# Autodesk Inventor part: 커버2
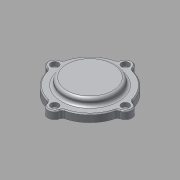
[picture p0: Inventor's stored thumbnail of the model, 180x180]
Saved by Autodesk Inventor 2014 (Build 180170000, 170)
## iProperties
Company: 한국ATC센터
Created: 2015-12
Part Number: 커버2
Document SubType Name: Modeling
Designer: mdu
Density: 2.71 g/cm^3
Material: 알루미늄 6061
Appearance: 알루미늄 - 평지
Author: mdu
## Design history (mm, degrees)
sketch "스케치1"
  geometry: C1 r 1.621 at (0, 6.75) reference; C2 r 1.621 at (-37, -30.25) reference; C3 r 1.621 at (0, -67.25) reference; C4 r 1.621 at (37, -30.25) reference; C5 r 10 at (0, -30.25) reference; C6 r 12 at (0, -30.25); C7 r 24.5 at (0, -30.25) reference; A1 r 3 centre (-38.77, -20.408) between (-38.239, -23.361) and (-35.862, -21.146) reference; A2 r 7 centre (-37, -30.25) between (-38.239, -23.361) and (-38.239, -37.139) reference; A3 r 3 centre (-38.77, -40.092) between (-35.862, -39.354) and (-38.239, -37.139) reference; A4 r 37 centre (0, -30.25) between (-35.862, -39.354) and (-9.104, -66.113) reference; A5 r 3 centre (-9.842, -69.02) between (-6.889, -68.489) and (-9.104, -66.113) reference; A6 r 7 centre (0, -67.25) between (-6.889, -68.489) and (6.889, -68.489) reference; A7 r 3 centre (9.842, -69.02) between (9.104, -66.112) and (6.889, -68.489) reference; A8 r 37 centre (0, -30.25) between (9.104, -66.112) and (35.863, -39.354) reference; A9 r 3 centre (38.77, -40.092) between (38.239, -37.139) and (35.863, -39.354) reference; A10 r 7 centre (37, -30.25) between (38.239, -37.139) and (38.239, -23.361) reference; A11 r 3 centre (38.77, -20.408) between (35.863, -21.146) and (38.239, -23.361) reference; A12 r 37 centre (0, -30.25) between (35.863, -21.146) and (9.104, 5.612) reference; A13 r 3 centre (9.842, 8.52) between (6.889, 7.989) and (9.104, 5.612) reference; A14 r 7 centre (0, 6.75) between (6.889, 7.989) and (-6.889, 7.989) reference; A15 r 3 centre (-9.842, 8.52) between (-9.104, 5.612) and (-6.889, 7.989) reference; A16 r 37 centre (0, -30.25) between (-9.104, 5.612) and (-35.862, -21.146) reference; 1 further point
  constraints: 1 centre point, 1 coincident
  dimensions: "d2" = 2 radial gap between concentric circles of C6 C5
extrude "돌출1" new body sketch "스케치1" distance "d0" = 8; taper "d1" = 0 deg
sketch "스케치2"
  geometry: C1 r 23.5 at (0, -30.25) reference; C2 r 12 at (0, -30.25) reference; 1 further point
extrude "돌출2" join sketch "스케치2" distance "d4" = 5; taper "d5" = 0 deg
sketch "스케치3"
  geometry: C1 r 23.5 at (0, 0) reference; C2 r 20.5 at (0, 0); 1 further point
  constraints: 1 centre point
  dimensions: "d6" = 3 radial gap between concentric circles of C2 C1
node "작업 평면1"
extrude "돌출3" join sketch "스케치3" stored distance "d7" = 5; taper "d8" = 0 deg
fillet "모깎기1" dims "d9" = 3
sketch "스케치4"
  geometry: C1 r 12 at (0, -30.25) reference; C2 r 27 at (0, -30.25); 1 further point
  constraints: 1 centre point
  dimensions: "d10" = 15 radial gap between concentric circles of C1 C2
extrude "돌출4" join sketch "스케치4" distance "d11" = 7; taper "d12" = 0 deg
fillet "모깎기2" dims "d13" = 3
chamfer "모따기1" distance "d14" = 1; stored, may be unused: second distance "d15" = 2, angle "d16" = 45 deg
node "작업점1"
  node "작업축1"
chamfer "모따기2" distance "d24" = 1; stored, may be unused: second distance "d25" = 2, angle "d26" = 45 deg
hole "구멍6" diameter "d43" = 4.5; stored, may be unused: countersink angle "d47" = 90 deg, drill point angle "d49" = 118 deg; dims "d41" = 10, "d42" = 10, "d44" = 6, "d45" = 8, "d46" = 4.4, "d48" = 8
fillet "모깎기4" dims "d60" = 3
node "솔리드1"
pattern_circular "원형 패턴1" dims angle "d51" = 360 deg
node "참조1"
node "참조2"
